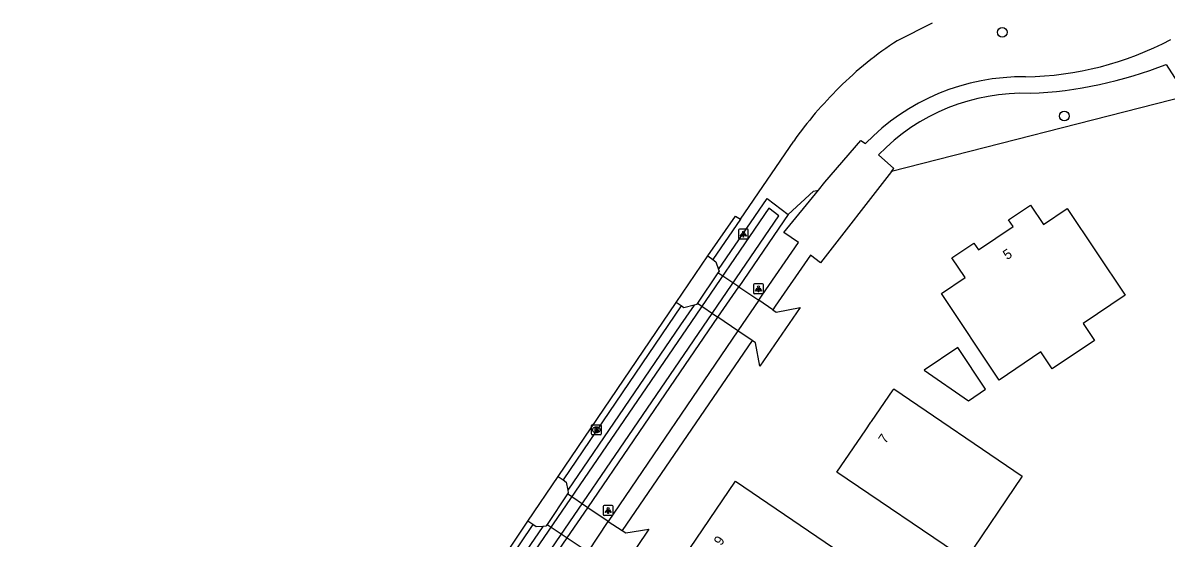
# Model space of a CAD drawing. Extents: x 158797 to 159887, y 384318 to 385255.
# Drawn here: x 158933.1 to 159049.4, y 384893.5 to 384945.9 of the extents above; entities that cross this region are included whole.
import ezdxf

# ---------------------------------------------------------------- set-up
doc = ezdxf.new("R2010")
doc.units = 0
for name, color, linetype in [('IMGEO_Berm_groen', 7, 'Continuous'), ('IMGEO_Boom', 7, 'Continuous'), ('IMGEO_Brandkraan', 7, 'Continuous'), ('IMGEO_Greppel_droge_sloot', 7, 'Continuous'), ('IMGEO_Groenvoorziening', 7, 'Continuous'), ('IMGEO_Lichtpunt', 7, 'Continuous'), ('IMGEO_Pand', 7, 'Continuous'), ('IMGEO_Pand_nummerreeks', 7, 'Continuous'), ('IMGEO_Rijbaan_lokaal_gesloten', 7, 'Continuous'), ('IMGEO_Rijbaan_lokaal_halfverhard', 7, 'Continuous'), ('IMGEO_Rijbaan_lokaal_open', 7, 'Continuous'), ('IMGEO_Voetpad_gesloten', 7, 'Continuous')]:
    doc.layers.add(name, color=color, linetype=linetype)

msp = doc.modelspace()

# ---------------------------------------------------------------- linework, layer by layer
at = {"layer": 'IMGEO_Berm_groen'}
for points in [[(159010.93, 384926.39), (159013.51, 384928.75), (159014.02, 384928.88)], [(159003.85, 384920.8), (159008.8, 384928.03), (159010.93, 384926.39)]]:
    msp.add_lwpolyline(points, dxfattribs=at)
at = {"layer": 'IMGEO_Boom'}
for centre in [(159032.72, 384944.92), (159039.03, 384936.4)]:
    msp.add_circle(centre, 0.489, dxfattribs=at)
at = {"layer": 'IMGEO_Brandkraan'}
for p, q in [((158990.92, 384904.07), (158990.92, 384904.92)), ((158991, 384904.99), (158991.85, 384904.99)), ((158991.41, 384904.77), (158991.44, 384904.77)), ((158991.43, 384904.21), (158991.41, 384904.21)), ((158991.92, 384904.92), (158991.92, 384904.07)), ((158991.85, 384903.99), (158991, 384903.99))]:
    msp.add_line(p, q, dxfattribs=at)
for points in [[(158990.92, 384904.07), (158990.92, 384904.92)], [(158991, 384904.99), (158991.85, 384904.99)], [(158991.27, 384904.69), (158991.27, 384904.29), (158991.48, 384904.29)], [(158991.5, 384904.69), (158991.27, 384904.69)], [(158991.45, 384904.61), (158991.4, 384904.61), (158991.4, 384904.54)], [(158991.4, 384904.54), (158991.45, 384904.54)], [(158991.46, 384904.46), (158991.4, 384904.46), (158991.4, 384904.38)], [(158991.4, 384904.38), (158991.46, 384904.38)], [(158991.92, 384904.92), (158991.92, 384904.07)], [(158991.85, 384903.99), (158991, 384903.99)]]:
    msp.add_lwpolyline(points, dxfattribs=at)
for centre, radius, start, end in [((158991, 384904.92), 0.0765, 91.552, 178.448), ((158991, 384904.92), 0.0765, 91.552, 178.448), ((158991.45, 384904.57), 0.0379, 267.8285, 90.9355), ((158991.46, 384904.42), 0.0404, 269.8759, 90.5077), ((158991.49, 384904.54), 0.251, 268.6676, 293.5347), ((158991.51, 384904.55), 0.145, 59.4692, 91.5367), ((158991.53, 384904.6), 0.0922, 285.5137, 58.1501), ((158991.54, 384904.4), 0.105, 301.3115, 78.989), ((158991.85, 384904.92), 0.0765, 1.552, 88.448), ((158991.85, 384904.92), 0.0765, 1.552, 88.448), ((158991, 384904.07), 0.0765, 181.552, 268.448), ((158991, 384904.07), 0.0765, 181.552, 268.448), ((158991.85, 384904.07), 0.0765, 271.552, 358.448), ((158991.85, 384904.07), 0.0765, 271.552, 358.448)]:
    msp.add_arc(centre, radius, start, end, dxfattribs=at)
for centre, major_axis, ratio, start_param, end_param in [((158991.41, 384904.49), (-0.387, 0.002), 0.722429, 4.712389, 7.853982), ((158991.43, 384904.49), (-0.39, 0.002), 0.717154, 1.570796, 4.712389)]:
    msp.add_ellipse(centre, major_axis=major_axis, ratio=ratio, start_param=start_param, end_param=end_param, dxfattribs=at)
at = {"layer": 'IMGEO_Greppel_droge_sloot'}
msp.add_lwpolyline([(158934.17, 384815.3), (158999.42, 384910.78), (159009.98, 384926.24), (159008.96, 384927.02), (159000.58, 384914.77), (158933.08, 384816.06)], dxfattribs=at)
at = {"layer": 'IMGEO_Groenvoorziening'}
for points in [[(159051.48, 384938.42), (159021.44, 384930.77)], [(159010.93, 384926.39), (159005.91, 384919.04)], [(159001.38, 384917.18), (159000, 384915.16), (158988.51, 384898.36)], [(158990.56, 384896.57), (159000, 384910.39), (159003.79, 384915.94)], [(158985.98, 384894.67), (158980.53, 384886.7)], [(158982.46, 384884.72), (158988.46, 384893.5)]]:
    msp.add_lwpolyline(points, dxfattribs=at)
at = {"layer": 'IMGEO_Lichtpunt'}
for p, q in [((159005.89, 384924.8), (159005.89, 384923.99)), ((159005.89, 384924.8), (159005.89, 384923.99)), ((159006.79, 384924.89), (159005.98, 384924.89)), ((159006.79, 384924.89), (159005.98, 384924.89)), ((159006.88, 384923.99), (159006.88, 384924.8)), ((159006.88, 384923.99), (159006.88, 384924.8)), ((159005.98, 384923.9), (159006.79, 384923.9)), ((159005.98, 384923.9), (159006.79, 384923.9)), ((159008.32, 384919.34), (159007.52, 384919.34)), ((159008.32, 384919.34), (159007.52, 384919.34)), ((159007.42, 384919.24), (159007.42, 384918.43)), ((159007.42, 384919.24), (159007.42, 384918.43)), ((159007.52, 384918.34), (159008.32, 384918.34)), ((159007.52, 384918.34), (159008.32, 384918.34)), ((159008.42, 384918.43), (159008.42, 384919.24)), ((159008.42, 384918.43), (159008.42, 384919.24)), ((158992.13, 384896.7), (158992.13, 384895.89)), ((158992.13, 384896.7), (158992.13, 384895.89)), ((158993.03, 384896.79), (158992.23, 384896.79)), ((158993.03, 384896.79), (158992.23, 384896.79)), ((158993.13, 384895.89), (158993.13, 384896.7)), ((158993.13, 384895.89), (158993.13, 384896.7)), ((158992.23, 384895.8), (158993.03, 384895.8)), ((158992.23, 384895.8), (158993.03, 384895.8))]:
    msp.add_line(p, q, dxfattribs=at)
for points in [[(159006.26, 384924.46), (159006.3, 384924.44), (159006.11, 384924.17), (159006.07, 384924.2), (159006.26, 384924.46)], [(159006.36, 384924.42), (159006.41, 384924.42), (159006.41, 384924.09), (159006.36, 384924.09), (159006.36, 384924.42)], [(159006.47, 384924.44), (159006.51, 384924.46), (159006.7, 384924.2), (159006.66, 384924.17), (159006.47, 384924.44)], [(159007.8, 384918.9), (159007.84, 384918.88), (159007.65, 384918.61), (159007.61, 384918.64), (159007.8, 384918.9)], [(159007.9, 384918.86), (159007.95, 384918.86), (159007.95, 384918.53), (159007.9, 384918.53), (159007.9, 384918.86)], [(159008.01, 384918.88), (159008.05, 384918.9), (159008.23, 384918.64), (159008.2, 384918.61), (159008.01, 384918.88)], [(158992.51, 384896.36), (158992.54, 384896.33), (158992.36, 384896.07), (158992.32, 384896.1), (158992.51, 384896.36)], [(158992.61, 384896.31), (158992.66, 384896.31), (158992.66, 384895.99), (158992.61, 384895.99), (158992.61, 384896.31)], [(158992.72, 384896.33), (158992.76, 384896.36), (158992.94, 384896.1), (158992.9, 384896.07), (158992.72, 384896.33)]]:
    msp.add_lwpolyline(points, dxfattribs=at)
for centre in [(159006.39, 384924.6), (159007.92, 384919.04), (158992.63, 384896.5)]:
    msp.add_circle(centre, 0.0994, dxfattribs=at)
for centre, start, end in [((159005.98, 384924.8), 90, 180), ((159005.98, 384924.8), 90, 180), ((159005.98, 384923.99), 180, 270), ((159005.98, 384923.99), 180, 270), ((159006.79, 384924.8), 0, 90), ((159006.79, 384924.8), 0, 90), ((159006.79, 384923.99), 270, 0), ((159006.79, 384923.99), 270, 360), ((159007.52, 384919.24), 90, 180), ((159007.52, 384919.24), 90, 180), ((159008.32, 384919.24), 0, 90), ((159008.32, 384919.24), 0, 90), ((159007.52, 384918.43), 180, 270), ((159007.52, 384918.43), 180, 270), ((159008.32, 384918.43), 270, 0), ((159008.32, 384918.43), 270, 360), ((158992.23, 384896.7), 90, 180), ((158992.23, 384896.7), 90, 180), ((158993.03, 384896.7), 0, 90), ((158993.03, 384896.7), 0, 90), ((158992.23, 384895.89), 180, 270), ((158992.23, 384895.89), 180, 270), ((158993.03, 384895.89), 270, 0), ((158993.03, 384895.89), 270, 360)]:
    msp.add_arc(centre, 0.0946, start, end, dxfattribs=at)
at = {"layer": 'IMGEO_Pand'}
for points in [[(159026.54, 384918.36), (159028.95, 384919.97), (159027.6, 384921.99), (159029.83, 384923.49), (159030.29, 384922.79), (159033.83, 384925.16), (159033.37, 384925.86), (159035.59, 384927.35), (159036.91, 384925.38), (159039.32, 384926.99), (159045.23, 384918.18), (159040.95, 384915.32), (159042.11, 384913.59), (159037.81, 384910.71), (159036.66, 384912.44), (159032.42, 384909.54), (159026.54, 384918.36)], [(159028.21, 384912.85), (159024.77, 384910.55), (159029.28, 384907.45), (159031.03, 384908.62), (159028.21, 384912.85)], [(159015.88, 384900.19), (159018.83, 384904.5), (159019.36, 384905.27), (159019.42, 384905.35), (159021.62, 384908.55), (159021.68, 384908.64), (159021.69, 384908.66), (159034.76, 384899.79), (159029, 384891.29), (159015.88, 384900.19)], [(159011.04, 384888.77), (159006.87, 384882.64), (158999.67, 384887.52), (159001.7, 384890.51), (159000.29, 384891.47), (159005.59, 384899.26), (159025.42, 384885.77), (159020.36, 384878.3), (159015.73, 384881.45), (159017.65, 384884.29), (159011.04, 384888.77)]]:
    msp.add_lwpolyline(points, dxfattribs=at)
at = {"layer": 'IMGEO_Rijbaan_lokaal_gesloten'}
for points in [[(159022.05, 384944.07), (159025.62, 384945.88)], [(159006.1, 384925.91), (159011.51, 384933.86)], [(159002.78, 384922.17), (159005.57, 384926.23), (159006.1, 384925.91)], [(158999.54, 384917.43), (159002.78, 384922.17)], [(159001.7, 384917.36), (159003.79, 384915.94), (159005.91, 384919.04), (159003.8, 384920.46), (159001.7, 384917.36)], [(159003.79, 384915.94), (159005.91, 384919.04)], [(159005.91, 384919.04), (159007.94, 384917.67)], [(158987.55, 384899.76), (158999.54, 384917.43)], [(159007.94, 384917.67), (159005.83, 384914.57)], [(159005.83, 384914.57), (159003.79, 384915.94)], [(158984.46, 384895.21), (158987.54, 384899.74), (158987.55, 384899.76)], [(158986.42, 384894.87), (158988.46, 384893.5), (158990.56, 384896.57), (158988.48, 384897.97), (158986.42, 384894.87)], [(158988.46, 384893.5), (158990.56, 384896.57)], [(158992.62, 384895.18), (158990.56, 384896.57)], [(158979.68, 384888.06), (158979.68, 384888.06), (158984.46, 384895.21)], [(158990.58, 384892.08), (158992.62, 384895.18)], [(158988.46, 384893.5), (158990.58, 384892.08)]]:
    msp.add_lwpolyline(points, dxfattribs=at)
for centre, radius, start, end in [((159041.17, 384914.3), 35.38, 122.7235, 135.0394), ((159043.16, 384911.59), 38.7, 134.2768, 144.872)]:
    msp.add_arc(centre, radius, start, end, dxfattribs=at)
at = {"layer": 'IMGEO_Rijbaan_lokaal_halfverhard'}
for points in [[(159006.1, 384925.91), (159003.26, 384921.81)], [(159000.04, 384917.09), (158988.04, 384899.41)], [(158984.96, 384894.87), (158980.16, 384887.7)]]:
    msp.add_lwpolyline(points, dxfattribs=at)
at = {"layer": 'IMGEO_Rijbaan_lokaal_open'}
for points in [[(159002.78, 384922.17), (159003.26, 384921.81)], [(159003.26, 384921.81), (159003.57, 384921.58), (159003.85, 384920.8)], [(159003.85, 384920.8), (159003.92, 384920.63), (159003.8, 384920.46), (159001.7, 384917.36), (159001.62, 384917.25), (159001.38, 384917.18)], [(159000.04, 384917.09), (158999.54, 384917.43)], [(159001.38, 384917.18), (159000.31, 384916.91), (159000.04, 384917.09)], [(159009.38, 384916.7), (159007.94, 384917.67)], [(159009.38, 384916.7), (159009.72, 384916.47), (159012.16, 384916.92), (159008.04, 384910.98), (159007.62, 384913.35), (159007.28, 384913.58)], [(159007.28, 384913.58), (159005.83, 384914.57)], [(158987.55, 384899.76), (158988.04, 384899.41)], [(158988.04, 384899.41), (158988.36, 384899.18), (158988.51, 384898.36)], [(158988.51, 384898.36), (158988.56, 384898.1), (158988.48, 384897.97), (158986.42, 384894.87), (158986.3, 384894.68), (158985.98, 384894.67)], [(158984.96, 384894.87), (158984.46, 384895.21)], [(158992.62, 384895.18), (158994.05, 384894.26)], [(158985.98, 384894.67), (158985.31, 384894.64), (158984.96, 384894.87)], [(158994.05, 384894.26), (158994.41, 384894.02), (158996.77, 384894.4), (158992.86, 384888.6), (158992.31, 384890.89), (158992, 384891.1)]]:
    msp.add_lwpolyline(points, dxfattribs=at)
at = {"layer": 'IMGEO_Voetpad_gesloten'}
for points in [[(159049.39, 384941.65), (159051.48, 384938.42)], [(159014.02, 384928.88), (159014.68, 384929.69), (159018.32, 384933.91), (159018.8, 384933.6)], [(159021.44, 384930.77), (159021.69, 384931.08), (159020.13, 384932.46)], [(159021.44, 384930.77), (159014.24, 384921.49), (159013.2, 384922.27), (159009.62, 384917.07), (159009.38, 384916.7)], [(159007.94, 384917.67), (159008.29, 384918.2), (159012, 384923.55), (159010.51, 384924.56), (159014.02, 384928.88)], [(159005.83, 384914.57), (158992.62, 384895.18)], [(159007.28, 384913.58), (158994.05, 384894.26)]]:
    msp.add_lwpolyline(points, dxfattribs=at)
for centre, radius, start, end in [((159034.47, 384973.47), 33.09, 271.0944, 297.7469), ((159033.66, 384981.72), 43.05, 272.552, 291.4215), ((159034.79, 384918.15), 22.24, 89.2094, 136.0044), ((159034.85, 384918.3), 20.42, 87.9585, 136.1231)]:
    msp.add_arc(centre, radius, start, end, dxfattribs=at)

# ---------------------------------------------------------------- texts
at = {"layer": 'IMGEO_Pand_nummerreeks'}
for s, rotation, p in [('5', 33.7243, (159033.21, 384921.74)), ('7', 55.5024, (159020.85, 384903.01)), ('9', 55.7946, (159004.12, 384892.65))]:
    msp.add_text(s, height=1, rotation=rotation, dxfattribs=at).set_placement(p)

doc.saveas('drawing.dxf')
